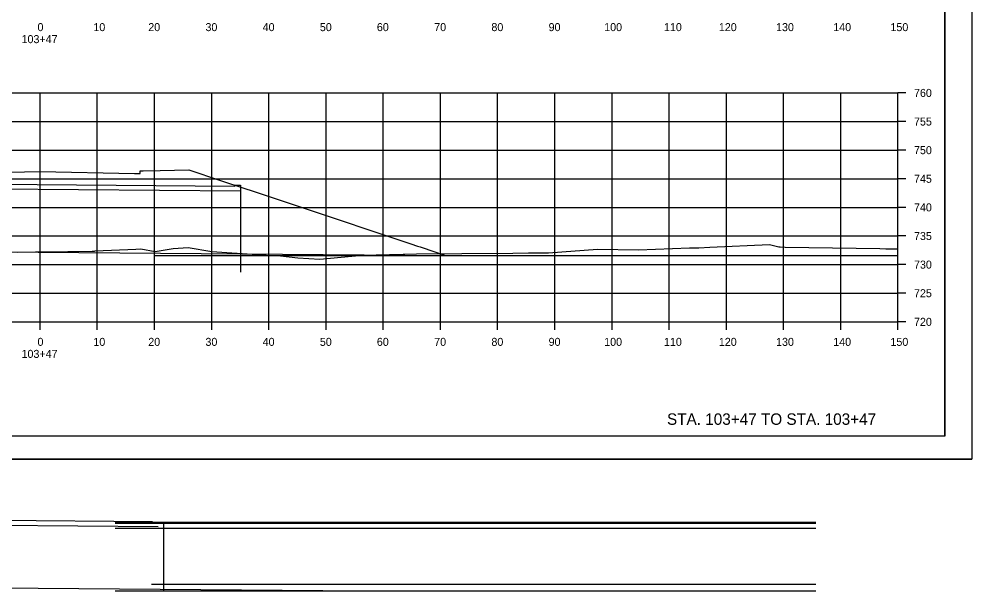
# Model space of a CAD drawing. Extents: x 1202951 to 1376887, y 378065 to 728038.
# Drawn here: x 1374940.6 to 1375107.2, y 378982.5 to 379082.4 of the extents above; entities that cross this region are included whole.
import ezdxf

# ---------------------------------------------------------------- set-up
doc = ezdxf.new("R2010")
doc.units = 0
for name, color, linetype in [('R_Axis', 7, 'Continuous'), ('R_Axis Annot', 7, 'Continuous'), ('R_Detour Annot', 7, 'Continuous'), ('R_Draft', 7, 'Continuous'), ('R_Exist Surface', 7, 'Continuous'), ('R_Fin Surface', 7, 'Continuous'), ('R_Grid', 7, 'Continuous'), ('R_No Plot', 7, 'Continuous')]:
    doc.layers.add(name, color=color, linetype=linetype)

msp = doc.modelspace()

# ---------------------------------------------------------------- linework, layer by layer
at = {"layer": 'R_Axis'}
for p, q in [((1375094.27, 379029.53), (1375094.27, 379069.53)), ((1375095.67, 379069.53), (1375094.27, 379069.53)), ((1375095.67, 379064.53), (1375094.27, 379064.53)), ((1375095.67, 379059.53), (1375094.27, 379059.53)), ((1375095.67, 379054.53), (1375094.27, 379054.53)), ((1375095.67, 379049.53), (1375094.27, 379049.53)), ((1375095.67, 379044.53), (1375094.27, 379044.53)), ((1375095.67, 379039.53), (1375094.27, 379039.53)), ((1375095.67, 379034.53), (1375094.27, 379034.53)), ((1374794.27, 379029.53), (1375094.27, 379029.53)), ((1374944.27, 379028.13), (1374944.27, 379029.53)), ((1374954.27, 379028.13), (1374954.27, 379029.53)), ((1374964.27, 379028.13), (1374964.27, 379029.53)), ((1374974.27, 379028.13), (1374974.27, 379029.53)), ((1374984.27, 379028.13), (1374984.27, 379029.53)), ((1374994.27, 379028.13), (1374994.27, 379029.53)), ((1375004.27, 379028.13), (1375004.27, 379029.53)), ((1375014.27, 379028.13), (1375014.27, 379029.53)), ((1375024.27, 379028.13), (1375024.27, 379029.53)), ((1375034.27, 379028.13), (1375034.27, 379029.53)), ((1375044.27, 379028.13), (1375044.27, 379029.53)), ((1375054.27, 379028.13), (1375054.27, 379029.53)), ((1375064.27, 379028.13), (1375064.27, 379029.53)), ((1375074.27, 379028.13), (1375074.27, 379029.53)), ((1375084.27, 379028.13), (1375084.27, 379029.53)), ((1375094.27, 379028.13), (1375094.27, 379029.53)), ((1375095.67, 379029.53), (1375094.27, 379029.53))]:
    msp.add_line(p, q, dxfattribs=at)
at = {"layer": 'R_Detour Annot'}
for p, q in [((1374900.77, 379053.05), (1374979.29, 379052.42)), ((1374901.77, 379053.88), (1374978.29, 379053.26)), ((1374978.29, 379053.43), (1374979.29, 379053.42)), ((1374978.29, 379053.43), (1374978.29, 379053.26)), ((1374979.29, 379053.42), (1374979.29, 379038.22)), ((1374866.62, 379042.33), (1375015.18, 379041.13)), ((1374964.27, 379041.13), (1375094.27, 379041.13)), ((1374859.92, 378994.64), (1374964.93, 378993.79)), ((1374861.02, 378995.47), (1374963.93, 378994.64)), ((1374957.39, 378994.5), (1375079.91, 378994.5)), ((1374964.82, 378994.5), (1374965.82, 378994.5)), ((1374964.82, 378994.5), (1374964.82, 378994.34)), ((1374965.82, 378994.5), (1374965.82, 378982.5)), ((1374957.39, 378994.34), (1375079.91, 378994.34)), ((1374957.39, 378993.5), (1375079.91, 378993.5)), ((1374852.25, 378983.7), (1375000.82, 378982.5)), ((1374963.74, 378983.7), (1375079.91, 378983.7)), ((1374957.39, 378982.5), (1375079.91, 378982.5))]:
    msp.add_line(p, q, dxfattribs=at)
at = {"layer": 'R_Exist Surface'}
msp.add_lwpolyline([(1374940.39, 379041.7), (1374943.48, 379041.79), (1374944.74, 379041.74), (1374944.89, 379041.74), (1374953.39, 379041.89), (1374953.69, 379041.89), (1374953.77, 379041.9), (1374953.77, 379041.9), (1374953.78, 379041.9), (1374953.92, 379041.91), (1374960.99, 379042.2), (1374961.87, 379042.29), (1374964.36, 379041.82), (1374967.52, 379042.37), (1374970.18, 379042.51), (1374974.3, 379041.84), (1374982.22, 379041.27), (1374982.31, 379041.27), (1374982.39, 379041.26), (1374982.55, 379041.24), (1374986.33, 379041.06), (1374989.36, 379040.69), (1374993.19, 379040.49), (1375000.65, 379041.18), (1375010.1, 379041.4), (1375017.99, 379041.48), (1375026.95, 379041.53), (1375029.69, 379041.56), (1375033.16, 379041.57), (1375041.73, 379042.23), (1375048.91, 379042.12), (1375057.81, 379042.45), (1375059.45, 379042.44), (1375061.37, 379042.59), (1375071.83, 379043.03), (1375073.43, 379042.62), (1375073.69, 379042.61), (1375074.55, 379042.59), (1375091.09, 379042.36), (1375092.13, 379042.27), (1375094.27, 379042.3)], dxfattribs=at)
at = {"layer": 'R_Fin Surface'}
msp.add_lwpolyline([(1374916.77, 379055.24), (1374944.27, 379055.79), (1374960.77, 379055.46), (1374961.77, 379055.44), (1374961.78, 379055.94), (1374962.27, 379055.94), (1374965.27, 379056), (1374970.27, 379056.1), (1374975.83, 379054.25), (1374980.05, 379052.84), (1374981.37, 379052.4), (1374989.55, 379049.67), (1375009.09, 379043.16), (1375010.23, 379042.78), (1375010.72, 379042.62), (1375011.4, 379042.39), (1375012.6, 379041.99), (1375015.18, 379041.13)], dxfattribs=at)
at = {"layer": 'R_Grid'}
for p, q in [((1374794.27, 379069.53), (1375094.27, 379069.53)), ((1374944.27, 379029.53), (1374944.27, 379069.53)), ((1374954.27, 379029.53), (1374954.27, 379069.53)), ((1374964.27, 379029.53), (1374964.27, 379069.53)), ((1374974.27, 379029.53), (1374974.27, 379069.53)), ((1374984.27, 379029.53), (1374984.27, 379069.53)), ((1374994.27, 379029.53), (1374994.27, 379069.53)), ((1375004.27, 379029.53), (1375004.27, 379069.53)), ((1375014.27, 379029.53), (1375014.27, 379069.53)), ((1375024.27, 379029.53), (1375024.27, 379069.53)), ((1375034.27, 379029.53), (1375034.27, 379069.53)), ((1375044.27, 379029.53), (1375044.27, 379069.53)), ((1375054.27, 379029.53), (1375054.27, 379069.53)), ((1375064.27, 379029.53), (1375064.27, 379069.53)), ((1375074.27, 379029.53), (1375074.27, 379069.53)), ((1375084.27, 379029.53), (1375084.27, 379069.53)), ((1375094.27, 379029.53), (1375094.27, 379069.53)), ((1374794.27, 379064.53), (1375094.27, 379064.53)), ((1374794.27, 379059.53), (1375094.27, 379059.53)), ((1374794.27, 379054.53), (1375094.27, 379054.53)), ((1374794.27, 379049.53), (1375094.27, 379049.53)), ((1374794.27, 379044.53), (1375094.27, 379044.53)), ((1374794.27, 379039.53), (1375094.27, 379039.53)), ((1374794.27, 379034.53), (1375094.27, 379034.53)), ((1374794.27, 379029.53), (1375094.27, 379029.53))]:
    msp.add_line(p, q, dxfattribs=at)
at = {"layer": 'R_No Plot'}
for p, q in [((1375102.45, 379009.53), (1375102.45, 379214.99)), ((1375102.45, 379009.53), (1374786.27, 379009.53)), ((1374773.87, 379005.55), (1375107.2, 379005.55))]:
    msp.add_line(p, q, dxfattribs=at)
for points in [[(1374773.86, 379218.88), (1375107.2, 379218.88), (1375107.2, 379005.54), (1374773.86, 379005.54)], [(1375020.19, 379214.99), (1375039.81, 379214.99), (1375039.81, 379205.11), (1375055.92, 379205.11), (1375079.12, 379205.11), (1375079.12, 379180.77), (1375102.45, 379180.77), (1375102.45, 379009.53), (1374786.27, 379009.53), (1374786.27, 379214.99)]]:
    msp.add_lwpolyline(points, close=True, dxfattribs=at)

# ---------------------------------------------------------------- texts
at = {"layer": 'R_Axis Annot'}
for s, p in [('0', (1374943.81, 379080.33)), ('10', (1374953.58, 379080.33)), ('20', (1374963.18, 379080.33)), ('30', (1374973.18, 379080.33)), ('40', (1374983.18, 379080.33)), ('50', (1374993.18, 379080.33)), ('60', (1375003.15, 379080.33)), ('70', (1375013.18, 379080.33)), ('80', (1375023.18, 379080.33)), ('90', (1375033.18, 379080.33)), ('100', (1375042.9, 379080.33)), ('110', (1375053.35, 379080.33)), ('120', (1375062.95, 379080.33)), ('130', (1375072.95, 379080.33)), ('140', (1375082.95, 379080.33)), ('150', (1375092.95, 379080.33)), ('103+47', (1374941.02, 379078.23)), ('760', (1375097.07, 379068.83)), ('755', (1375097.07, 379063.83)), ('750', (1375097.07, 379058.83)), ('745', (1375097.07, 379053.83)), ('740', (1375097.07, 379048.83)), ('735', (1375097.07, 379043.83)), ('730', (1375097.07, 379038.83)), ('725', (1375097.07, 379033.83)), ('720', (1375097.07, 379028.83)), ('0', (1374943.81, 379025.33)), ('10', (1374953.58, 379025.33)), ('20', (1374963.18, 379025.33)), ('30', (1374973.18, 379025.33)), ('40', (1374983.18, 379025.33)), ('50', (1374993.18, 379025.33)), ('60', (1375003.15, 379025.33)), ('70', (1375013.18, 379025.33)), ('80', (1375023.18, 379025.33)), ('90', (1375033.18, 379025.33)), ('100', (1375042.9, 379025.33)), ('110', (1375053.35, 379025.33)), ('120', (1375062.95, 379025.33)), ('130', (1375072.95, 379025.33)), ('140', (1375082.95, 379025.33)), ('150', (1375092.95, 379025.33)), ('103+47', (1374941.02, 379023.23))]:
    msp.add_text(s, height=1.4, dxfattribs=at).set_placement(p)
at = {"layer": 'R_Draft'}
msp.add_text('STA. 103+47 TO STA. 103+47', height=2, dxfattribs=at).set_placement((1375053.88, 379011.53))

doc.saveas('drawing.dxf')
